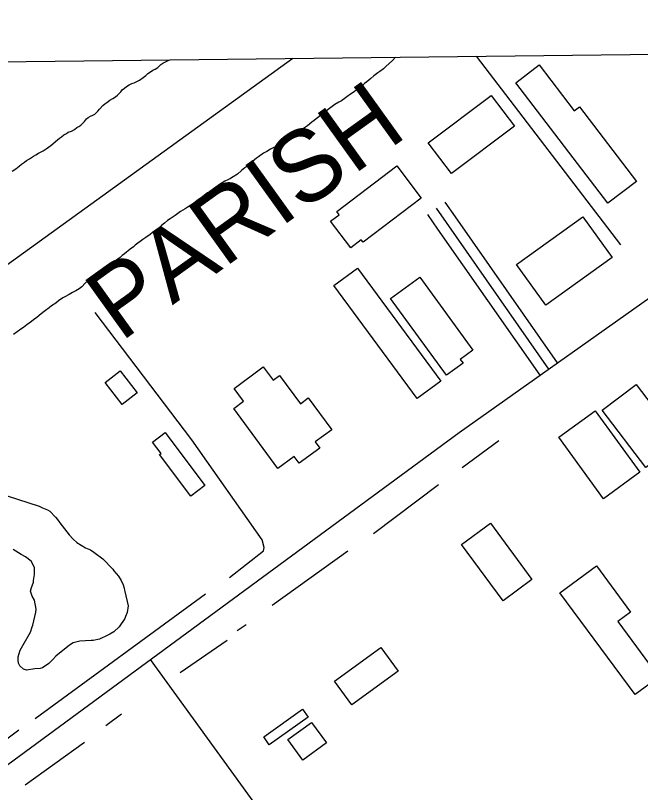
# Model space of a CAD drawing. Extents: x 3683613 to 3738215, y 469626 to 495384.
# Drawn here: x 3693268 to 3694144, y 492263 to 493352 of the extents above; entities that cross this region are included whole.
import ezdxf

# ---------------------------------------------------------------- set-up
doc = ezdxf.new("R2010")
doc.units = 0
for name, color, linetype in [('V-BLDG-OTLN', 7, 'Continuous'), ('V-GRID-FRAM', 7, 'Continuous'), ('V-ROAD-CNTR', 7, 'Continuous'), ('V-SITE-VEGE', 7, 'Continuous'), ('V-TOPO-BNDY', 7, 'Continuous'), ('V-TOPO-GNAM-IDEN', 7, 'Continuous'), ('V-TOPO-SHOR', 7, 'Continuous')]:
    doc.layers.add(name, color=color, linetype=linetype)

msp = doc.modelspace()

# ---------------------------------------------------------------- linework, layer by layer
at = {"layer": 'V-BLDG-OTLN'}
for points in [[(3694138.9, 493119.2), (3694098.9, 493088.7), (3693969.9, 493257.7), (3694002.6, 493282.6), (3694051.6, 493218.3), (3694059, 493224)], [(3693967.6, 493196.7), (3693879.3, 493130.2), (3693846.8, 493173.3), (3693935.2, 493239.8)], [(3693837, 493095.9), (3693755.5, 493034), (3693753, 493037.2), (3693738.4, 493026.1), (3693709.9, 493063.5), (3693721.9, 493072.6), (3693718.5, 493077), (3693802.8, 493141)], [(3694104.6, 493012.6), (3694011.6, 492946), (3693970.8, 493003), (3694063.7, 493069.6)], [(3693747.7, 492997.8), (3693864.6, 492839.4), (3693831.3, 492814.8), (3693714.4, 492973.2)], [(3693835.2, 492985), (3693909.6, 492882.9), (3693891.8, 492869.8), (3693895.6, 492864.5), (3693872.4, 492847.5), (3693794.1, 492955)], [(3693574.2, 492801), (3693587.9, 492811.1), (3693574.6, 492829.1), (3693615.5, 492859.3), (3693629.3, 492840.6), (3693638.3, 492847.2), (3693667.5, 492807.7), (3693678.5, 492815.9), (3693711.5, 492771.3), (3693688.2, 492754.1), (3693694.6, 492745.5), (3693665.7, 492724.2), (3693658.6, 492733.8), (3693636, 492717.1)], [(3693417.6, 492806.6), (3693393.7, 492837.5), (3693415, 492853.9), (3693438.8, 492823)], [(3694090.9, 492798.6), (3694138.4, 492834.6), (3694199.5, 492754.1), (3694152.1, 492718.1)], [(3694029.9, 492760.9), (3694081, 492797.9), (3694143.6, 492711.6), (3694092.5, 492674.5)], [(3693478, 492767.2), (3693533.5, 492693.1), (3693513.7, 492678.3), (3693470.2, 492736.4), (3693472.1, 492737.9), (3693460.2, 492753.8)], [(3693893.5, 492610.4), (3693934, 492640.3), (3693992.2, 492561.4), (3693951.7, 492531.5)], [(3694031.3, 492542.7), (3694082.6, 492580.5), (3694130.5, 492515.5), (3694112.7, 492502.4), (3694170.2, 492424.5), (3694136.8, 492399.9)], [(3693715.4, 492418.6), (3693780.5, 492466), (3693804.7, 492432.8), (3693739.6, 492385.4)], [(3693616.1, 492340.5), (3693670.6, 492379.3), (3693678.3, 492368.5), (3693623.8, 492329.7)], [(3693650, 492336.8), (3693683.3, 492361), (3693704.2, 492332.2), (3693670.8, 492308)]]:
    msp.add_lwpolyline(points, close=True, dxfattribs=at)
at = {"layer": 'V-GRID-FRAM'}
msp.add_lwpolyline([(3687651.7, 493221.8), (3719350.3, 493590.7), (3719569.8, 475409.4), (3687855.3, 475040.3), (3687651.7, 493221.8)], dxfattribs=at)
at = {"layer": 'V-ROAD-CNTR'}
for points in [[(3693885, 493069.8), (3693870.7, 493090.3)], [(3694015.9, 492856.3), (3693858.4, 493081.7)], [(3693860.4, 493052.6), (3693846.1, 493073.1)], [(3694028.2, 492864.9), (3693885, 493069.8)], [(3693012.6, 492122.7), (3693890.2, 492767.4), (3694199.1, 492985.8), (3694277.9, 493044.8)], [(3694003.6, 492847.7), (3693860.4, 493052.6)], [(3693456.8, 492449), (3693733.5, 492067.6), (3693875.7, 491885.6)]]:
    msp.add_lwpolyline(points, dxfattribs=at)
at = {"layer": 'V-SITE-VEGE'}
msp.add_lwpolyline([(3693256.3, 492678.5), (3693301.3, 492663.9), (3693306, 492661.8), (3693312.8, 492658.8), (3693316.3, 492657.1), (3693324.1, 492648.8), (3693326.8, 492645.5), (3693330.3, 492640.6), (3693343.5, 492624.1), (3693348.9, 492617.9), (3693354, 492613), (3693366.2, 492605.8), (3693373, 492602.7), (3693378.1, 492599.8), (3693390.7, 492590.2), (3693404.3, 492575.7), (3693405.9, 492573.6), (3693412.5, 492565.8), (3693416.3, 492559.7), (3693419, 492554), (3693420.4, 492549.1), (3693421.1, 492546.3), (3693421.5, 492544.3), (3693426.1, 492524.4), (3693424.6, 492515.2), (3693422.5, 492509.3), (3693421.2, 492506.5), (3693413.2, 492494.7), (3693405.8, 492488.1), (3693400.4, 492484.6), (3693397.6, 492483.1), (3693385.8, 492477.4), (3693376.9, 492475.7), (3693374.1, 492475.7), (3693358.4, 492474.6), (3693349.1, 492472.5), (3693343.7, 492469.4), (3693341.3, 492467.5), (3693324.8, 492453.9), (3693320.6, 492449.2), (3693314.8, 492443.3), (3693305.8, 492437.6), (3693302.6, 492436.5), (3693295.3, 492435.9), (3693283.6, 492434.2), (3693279.2, 492435.5), (3693274.2, 492440.1), (3693272.3, 492444.2), (3693271.6, 492448.2), (3693271.7, 492453), (3693274.8, 492462.2), (3693278.2, 492468.9), (3693289.2, 492487.5), (3693291.5, 492495.1), (3693292.3, 492497.4), (3693296.5, 492515.4), (3693297, 492519.8), (3693294.6, 492532.3), (3693291.5, 492538.1), (3693289.3, 492544.9), (3693290.3, 492550.1), (3693291.5, 492552.5), (3693293.3, 492557.7), (3693293.4, 492559.7), (3693294.8, 492568.5), (3693294.6, 492574.5), (3693294.7, 492578.1), (3693289.8, 492587.1), (3693281.9, 492593), (3693276, 492596.4), (3693264.9, 492603.1)], dxfattribs=at)
at = {"layer": 'V-TOPO-BNDY'}
msp.add_lwpolyline([(3693656.8, 493291.7), (3692798.1, 492671.4), (3692256.2, 492404.1), (3691475.1, 492125.6), (3691044.3, 491992.1), (3690569.3, 491705.8), (3690167.2, 491293.5), (3689620.1, 490480.7), (3689391.4, 490221.7), (3689222.7, 490096.9), (3688304.5, 489656.3), (3687696.1, 489259.4)], dxfattribs=at)
at = {"layer": 'V-TOPO-SHOR'}
for p, q in [((3694117.1, 493030.2), (3693914.3, 493294.7)), ((3693946, 492755.7), (3693894.5, 492717.6)), ((3693861.3, 492694.1), (3693770.2, 492625.4)), ((3693734.1, 492601.2), (3693628.1, 492524.8)), ((3693534.5, 492540.7), (3693295.6, 492366.1)), ((3693591.3, 492497.6), (3693578.8, 492489.5)), ((3693564.9, 492475.7), (3693498.8, 492430.6)), ((3693416.5, 492372.3), (3693394.8, 492356.1)), ((3693272.9, 492349.9), (3693220.1, 492311.5)), ((3693365, 492333), (3693281.6, 492273))]:
    msp.add_line(p, q, dxfattribs=at)
for points in [[(3693263.5, 493133.9), (3693268.4, 493136.9), (3693273.3, 493140.9), (3693276.5, 493143.7), (3693280.5, 493146.5), (3693283.3, 493148.5), (3693287.7, 493150.9), (3693293.3, 493154.9), (3693296.6, 493156.6), (3693300.4, 493158.8), (3693303.2, 493160.4), (3693306.8, 493162.4), (3693311.2, 493164.9), (3693317.8, 493169.7), (3693320.4, 493172), (3693324.2, 493175.4), (3693327, 493177.6), (3693329.6, 493179.8), (3693332.4, 493182), (3693336, 493184.6), (3693339.6, 493186.6), (3693342.1, 493188.4), (3693346.7, 493189.9), (3693350.6, 493192.1), (3693354.2, 493194.7), (3693356.9, 493196.5), (3693359.7, 493198.1), (3693362, 493200.3), (3693364.6, 493203.3), (3693367.6, 493206.8), (3693370, 493208.8), (3693373.2, 493210.8), (3693376.3, 493212.1), (3693379.3, 493213.5), (3693383.6, 493218), (3693385.8, 493220.8), (3693390.3, 493225.7), (3693393.2, 493228.1), (3693396.2, 493230.1), (3693400.5, 493233.1), (3693404.7, 493235.5), (3693408.1, 493237.9), (3693410.9, 493240.3), (3693413.2, 493242.5), (3693415.8, 493245.1), (3693417.8, 493247.6), (3693421, 493250.2), (3693423.9, 493252.4), (3693427.6, 493254.8), (3693431.1, 493256.5), (3693434.3, 493257.7), (3693438.3, 493259.4), (3693441.9, 493261.4), (3693447, 493265.2), (3693451, 493268), (3693453.8, 493270.4), (3693457.4, 493272.8), (3693460.8, 493275.2), (3693464, 493276.8), (3693467.6, 493279.2), (3693471.7, 493283), (3693474.7, 493285), (3693482.9, 493289.1), (3693483.8, 493289.7)], [(3693801, 493293.4), (3693800.9, 493293.3), (3693796.8, 493288.6), (3693787.2, 493280.4), (3693783.9, 493277.3), (3693779, 493273.3), (3693776.3, 493271.5), (3693770.5, 493267.1), (3693766.5, 493263.5), (3693760.7, 493258.9), (3693757.3, 493256.5), (3693751.8, 493251.6), (3693747.5, 493248.6), (3693741.5, 493244), (3693737.7, 493241.4), (3693732.8, 493238), (3693725, 493232.2), (3693721.4, 493230.3), (3693715.8, 493226.9), (3693706.7, 493220.3), (3693703.5, 493217.7), (3693700.5, 493215.5), (3693697.5, 493213.3), (3693689.9, 493207), (3693686.7, 493204.6), (3693683.7, 493202.2), (3693677.3, 493197.4), (3693670.3, 493192.6), (3693666.9, 493189.8), (3693657.7, 493183.4), (3693654.3, 493180.8), (3693651.1, 493178.4), (3693639.7, 493171.7), (3693636.9, 493170.3), (3693632.3, 493168), (3693625.7, 493164.4), (3693620.7, 493161.4), (3693615.8, 493158.7), (3693608.8, 493153.9), (3693606.2, 493151.9), (3693600, 493146.8), (3693596.2, 493143.6), (3693592.3, 493140.2), (3693589.8, 493138.4), (3693584.9, 493134.4), (3693579.3, 493129.5), (3693573.4, 493125.6), (3693569.4, 493123.4), (3693565.6, 493121.6), (3693561.8, 493119.5), (3693554.3, 493115.1), (3693549.2, 493111.1), (3693540.7, 493105.3), (3693537.3, 493103.1), (3693532.9, 493099.9), (3693530.1, 493097.9), (3693522.9, 493092.5), (3693517.5, 493088.3), (3693513.9, 493086.1), (3693508.8, 493082.9), (3693505.9, 493080.9), (3693502.9, 493079.1), (3693499.5, 493077.2)], [(3693801, 493293.4), (3693800.9, 493293.3), (3693796.8, 493288.6), (3693787.2, 493280.4), (3693783.9, 493277.3), (3693779, 493273.3), (3693776.3, 493271.5), (3693770.5, 493267.1), (3693766.5, 493263.5), (3693760.7, 493258.9), (3693757.3, 493256.5), (3693751.8, 493251.6), (3693747.5, 493248.6), (3693741.5, 493244), (3693737.7, 493241.4), (3693732.8, 493238), (3693725, 493232.2), (3693721.4, 493230.3), (3693715.8, 493226.9), (3693706.7, 493220.3), (3693703.5, 493217.7), (3693700.5, 493215.5), (3693697.5, 493213.3)], [(3693697.5, 493213.3), (3693689.9, 493207), (3693686.7, 493204.6), (3693683.7, 493202.2), (3693677.3, 493197.4), (3693670.3, 493192.6), (3693666.9, 493189.8), (3693657.7, 493183.4), (3693654.3, 493180.8), (3693651.1, 493178.4), (3693639.7, 493171.7), (3693636.9, 493170.3), (3693632.3, 493168), (3693625.7, 493164.4), (3693620.7, 493161.4), (3693615.8, 493158.7), (3693608.8, 493153.9), (3693606.2, 493151.9), (3693600, 493146.8), (3693596.2, 493143.6), (3693592.3, 493140.2), (3693589.8, 493138.4), (3693584.9, 493134.4), (3693579.3, 493129.5), (3693573.4, 493125.6), (3693569.4, 493123.4), (3693565.6, 493121.6), (3693561.8, 493119.5), (3693554.3, 493115.1), (3693549.2, 493111.1), (3693540.7, 493105.3), (3693537.3, 493103.1), (3693532.9, 493099.9), (3693530.1, 493097.9), (3693522.9, 493092.5), (3693517.5, 493088.3), (3693513.9, 493086.1), (3693508.8, 493082.9), (3693505.9, 493080.9), (3693502.9, 493079.1), (3693499.5, 493077.2), (3693491.9, 493071.6), (3693487.6, 493068.8), (3693484.8, 493066.8), (3693481.2, 493064.4), (3693476.8, 493060.8), (3693472.7, 493057.6), (3693468.2, 493053.5), (3693460.1, 493047.7), (3693456.9, 493045.1), (3693450.8, 493040.7), (3693446.7, 493037.7), (3693435.9, 493029.9), (3693433.3, 493027.7), (3693428.8, 493024.3), (3693420.9, 493017.7), (3693417.8, 493015.3), (3693414.8, 493012.8), (3693406.9, 493007.2), (3693403.7, 493005.3), (3693398.4, 493002.3), (3693392.5, 492998.5), (3693385.7, 492992.9), (3693381.6, 492989.9), (3693376.3, 492986.3), (3693373.3, 492984.5), (3693365.6, 492976.6), (3693360.9, 492971.4), (3693357.1, 492968.8), (3693352.6, 492966), (3693348.2, 492963.6), (3693343.1, 492960.6), (3693337.2, 492957.7), (3693334.6, 492956.1), (3693328.5, 492951.9), (3693324.4, 492948.7), (3693318.7, 492944.7), (3693315.3, 492942.3), (3693310.2, 492938.5), (3693306.5, 492935.7), (3693301.4, 492931.5), (3693297.8, 492928.5), (3693293.1, 492925.1), (3693290.5, 492923.1), (3693284, 492918.3), (3693279.3, 492914.6), (3693275.7, 492912.3), (3693265.4, 492904.9)], [(3693499.5, 493077.2), (3693491.9, 493071.6), (3693487.6, 493068.8), (3693484.8, 493066.8), (3693481.2, 493064.4), (3693476.8, 493060.8), (3693472.7, 493057.6), (3693468.2, 493053.5), (3693460.1, 493047.7), (3693456.9, 493045.1), (3693450.8, 493040.7), (3693446.7, 493037.7), (3693435.9, 493029.9), (3693433.3, 493027.7), (3693428.8, 493024.3), (3693420.9, 493017.7), (3693417.8, 493015.3), (3693414.8, 493012.8), (3693406.9, 493007.2), (3693403.7, 493005.3), (3693398.4, 493002.3), (3693392.5, 492998.5), (3693385.7, 492992.9), (3693381.6, 492989.9), (3693376.3, 492986.3), (3693373.3, 492984.5), (3693365.6, 492976.6), (3693360.9, 492971.4), (3693357.1, 492968.8), (3693352.6, 492966), (3693348.2, 492963.6), (3693343.1, 492960.6), (3693337.2, 492957.7), (3693334.6, 492956.1), (3693328.5, 492951.9), (3693324.4, 492948.7), (3693318.7, 492944.7), (3693315.3, 492942.3), (3693310.2, 492938.5), (3693306.5, 492935.7), (3693301.4, 492931.5), (3693297.8, 492928.5), (3693293.1, 492925.1), (3693290.5, 492923.1), (3693284, 492918.3), (3693279.3, 492914.6), (3693275.7, 492912.3), (3693265.4, 492904.9)], [(3693568.1, 492563.9), (3693615.8, 492601.4), (3693616.6, 492606), (3693613.8, 492617.1), (3693515.3, 492757.2), (3693379.9, 492935.4)]]:
    msp.add_lwpolyline(points, dxfattribs=at)

# ---------------------------------------------------------------- texts
at = {"layer": 'V-TOPO-GNAM-IDEN'}
msp.add_text('PARISH', height=100, rotation=35.69, dxfattribs=at).set_placement((3693415.5, 492893.4))

doc.saveas('drawing.dxf')
